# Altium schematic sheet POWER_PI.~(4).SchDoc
size A; SheetNumber: 1; SheetTotal: 2
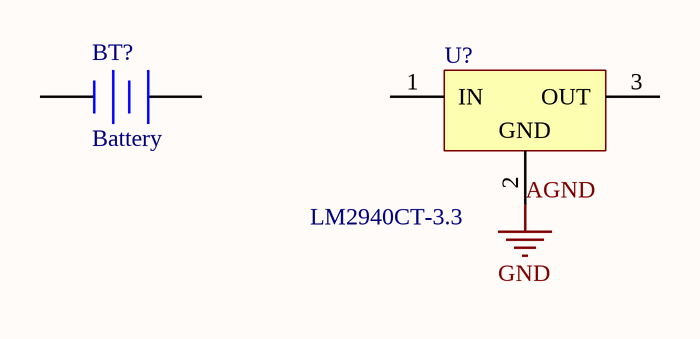
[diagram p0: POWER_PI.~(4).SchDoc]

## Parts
BT?  Battery  [BAT-2]
U?  LM2940CT-3.3  [T03B]

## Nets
AGND: U?.2(GND)  [also labelled GND]

Not connected (* = marked no-connect by the designer): BT? 1(+) 2(-); U? 1(IN) 3(OUT)

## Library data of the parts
BT? = Battery: Multicell Battery
U? = LM2940CT-5.0: 1A Low Dropout Regulator, 3-pin TO-220; Manufacturer: National Semiconductor; PackageTopMarking: NSUZXYTTE#*LM2940CT*-5.0 P+; PowerWise: N; CompType: LDO IC; High-Reliability: Y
